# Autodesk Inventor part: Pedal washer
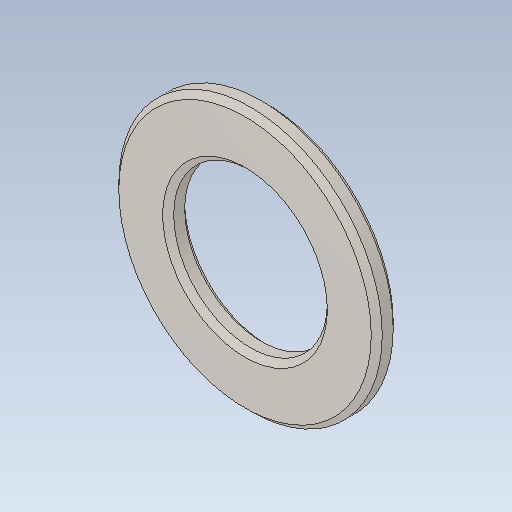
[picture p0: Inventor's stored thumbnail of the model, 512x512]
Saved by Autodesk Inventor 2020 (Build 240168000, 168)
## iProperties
Created: 2017-11
Part Number: Pedal washer
Material: solidworks materials|AISI 304|1
Document SubType Name: Modeling
Designer: Tomasz
Density: 8 g/cm^3
Appearance: 198,193,188
Sending System: SolidWorks 2017
Last Author: Tomasz
Last Saved: 2017-11-19
Author: Tomasz
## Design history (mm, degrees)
chamfer "Chamfer1"
node "Bryła1"
